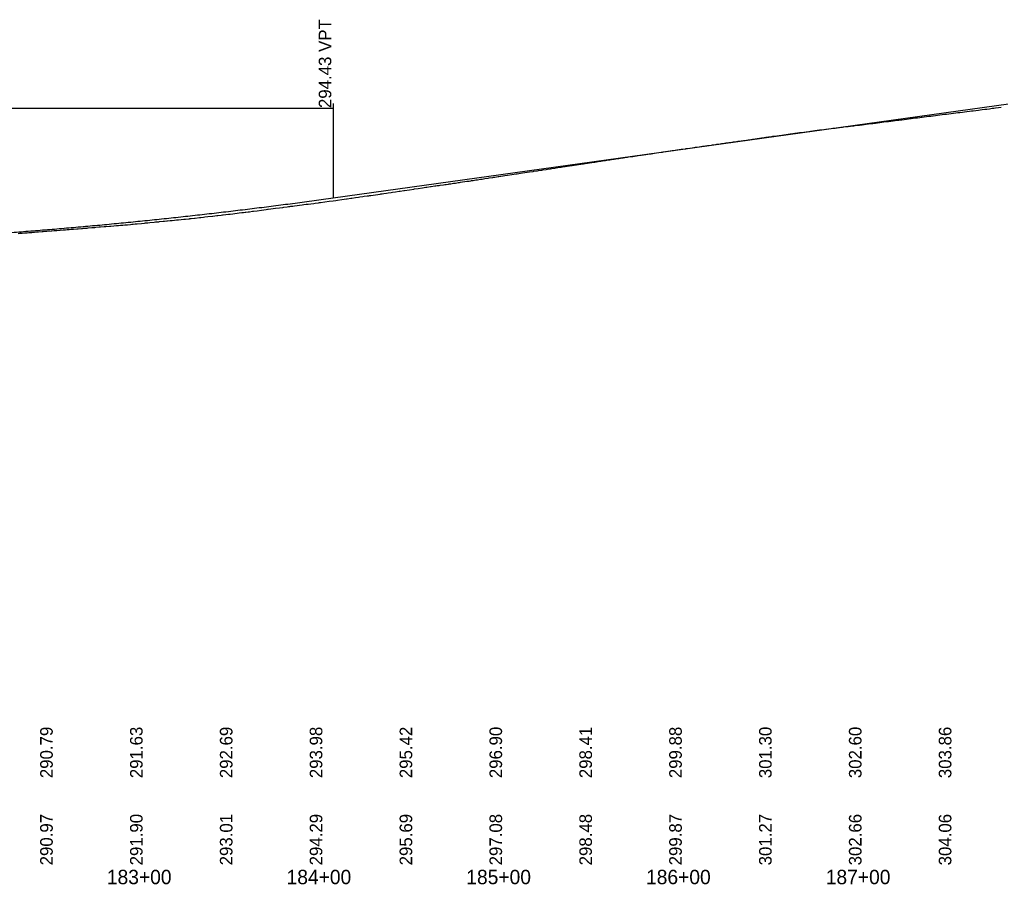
# Model space of a CAD drawing. Extents: x 1838386 to 1955906, y 719739 to 834437.
# Drawn here: x 1895594 to 1896139, y 826223 to 826704 of the extents above; entities that cross this region are included whole.
import ezdxf

# ---------------------------------------------------------------- set-up
doc = ezdxf.new("R2010")
doc.units = 0
for name, color, linetype in [('RD_DDB_Profile_EX', 7, 'Continuous'), ('RD_DDB_Profile_PR', 7, 'Continuous'), ('RD_DDB_StaTX', 7, 'Continuous'), ('RD_DDB_StripGrade', 7, 'Continuous'), ('RD_DDB_VCLbl', 7, 'Continuous')]:
    doc.layers.add(name, color=color, linetype=linetype)

msp = doc.modelspace()

# ---------------------------------------------------------------- linework, layer by layer
at = {"layer": 'RD_DDB_Profile_EX'}
for points in [[(1896023.79, 826641.09), (1896024.99, 826641.26), (1896026.44, 826641.45), (1896027.51, 826641.59), (1896028.76, 826641.75), (1896030, 826641.92), (1896031.24, 826642.09), (1896032.71, 826642.28), (1896033.71, 826642.41), (1896034.92, 826642.57), (1896036.19, 826642.74), (1896037.38, 826642.89), (1896038.67, 826643.06), (1896038.97, 826643.1), (1896039.85, 826643.21), (1896041.14, 826643.37), (1896042.32, 826643.51), (1896043.63, 826643.68), (1896045.24, 826643.89), (1896046.12, 826644), (1896047.47, 826644.17), (1896048.6, 826644.31), (1896049.74, 826644.45), (1896051.08, 826644.62), (1896051.5, 826644.67), (1896052.21, 826644.76), (1896053.56, 826644.92), (1896054.69, 826645.06), (1896056.04, 826645.23), (1896057.38, 826645.4), (1896057.77, 826645.44), (1896058.52, 826645.54), (1896059.88, 826645.7), (1896061.01, 826645.84), (1896062.39, 826646.01), (1896063.49, 826646.15), (1896064.04, 826646.22), (1896064.6, 826646.29), (1896065.97, 826646.46), (1896067.08, 826646.6), (1896068.44, 826646.77), (1896069.78, 826646.94), (1896070.3, 826647), (1896070.93, 826647.08), (1896072.32, 826647.26), (1896073.42, 826647.4), (1896074.54, 826647.54), (1896075.9, 826647.71), (1896076.57, 826647.79), (1896077.03, 826647.85), (1896078.37, 826648.01), (1896079.69, 826648.18), (1896080.86, 826648.33), (1896082.22, 826648.51), (1896082.83, 826648.59), (1896083.34, 826648.65), (1896084.49, 826648.8), (1896085.81, 826648.97), (1896087.1, 826649.13), (1896088.3, 826649.29), (1896089.1, 826649.39), (1896089.62, 826649.45), (1896090.79, 826649.6), (1896091.97, 826649.75), (1896093.26, 826649.9), (1896094.51, 826650.06), (1896095.36, 826650.17), (1896095.74, 826650.22), (1896097.02, 826650.38), (1896098.24, 826650.54), (1896099.46, 826650.7), (1896100.7, 826650.85), (1896101.63, 826650.97), (1896101.97, 826651.01), (1896103.2, 826651.17), (1896104.43, 826651.32), (1896105.71, 826651.49), (1896107, 826651.66), (1896108.19, 826651.81), (1896109.35, 826651.96), (1896110.7, 826652.12), (1896111.9, 826652.26), (1896113.21, 826652.44), (1896114.57, 826652.61), (1896115.69, 826652.75), (1896116.79, 826652.89), (1896118.21, 826653.07), (1896119.33, 826653.2), (1896120.7, 826653.37), (1896122.12, 826653.55), (1896123.2, 826653.67), (1896124.28, 826653.81), (1896125.71, 826653.99), (1896127.16, 826654.17), (1896128.18, 826654.29), (1896129.19, 826654.42), (1896130.7, 826654.61), (1896131.74, 826654.74), (1896133.2, 826654.93), (1896134.71, 826655.13), (1896135.7, 826655.25)], [(1896135.7, 826655.25), (1896136.7, 826655.38), (1896138.21, 826655.57), (1896139.76, 826655.77)], [(1895900.8, 826623.32), (1895901.14, 826623.37), (1895902.16, 826623.53), (1895903.44, 826623.72), (1895904.65, 826623.89), (1895905.85, 826624.07), (1895907.41, 826624.31), (1895908.27, 826624.44), (1895909.62, 826624.64), (1895910.67, 826624.8), (1895912.11, 826625.02), (1895913.08, 826625.17), (1895913.67, 826625.25), (1895914.59, 826625.39), (1895915.5, 826625.52), (1895917.07, 826625.76), (1895917.91, 826625.88), (1895919.56, 826626.13), (1895919.94, 826626.19), (1895920.32, 826626.25), (1895922.05, 826626.51), (1895923.85, 826626.77), (1895924.51, 826626.87), (1895926.4, 826627.16), (1895926.99, 826627.24), (1895928.96, 826627.54), (1895929.47, 826627.61), (1895931.51, 826627.91), (1895931.95, 826627.97), (1895932.47, 826628.05), (1895934.06, 826628.29), (1895934.44, 826628.34), (1895934.8, 826628.39), (1895936.91, 826628.71), (1895938.73, 826628.97), (1895939.4, 826629.07), (1895942.05, 826629.47), (1895944.48, 826629.82), (1895945, 826629.89), (1895946.9, 826630.17), (1895949.33, 826630.52), (1895951.26, 826630.8), (1895951.81, 826630.89), (1895954.3, 826631.24), (1895956.79, 826631.6), (1895957.53, 826631.71), (1895959.26, 826631.96), (1895961.75, 826632.31), (1895963.91, 826632.63), (1895964.24, 826632.67), (1895964.57, 826632.72), (1895966.72, 826633.01), (1895968.78, 826633.31), (1895969.2, 826633.37), (1895969.63, 826633.43), (1895970.06, 826633.49), (1895971.67, 826633.72), (1895973.65, 826634), (1895974.16, 826634.07), (1895976.32, 826634.38), (1895976.64, 826634.42), (1895978.53, 826634.69), (1895979.13, 826634.78), (1895980.96, 826635.04), (1895981.6, 826635.13), (1895982.59, 826635.27), (1895983.4, 826635.39), (1895984.09, 826635.48), (1895985.84, 826635.73), (1895986.57, 826635.84), (1895988.29, 826636.08), (1895989.05, 826636.18), (1895990.73, 826636.42), (1895991.53, 826636.54), (1895993.18, 826636.76), (1895994.01, 826636.88), (1895995.12, 826637.04), (1895995.62, 826637.11), (1895996.49, 826637.23), (1895998.06, 826637.44), (1895998.97, 826637.57), (1896000.51, 826637.79), (1896001.46, 826637.93), (1896002.96, 826638.14), (1896003.93, 826638.28), (1896005.41, 826638.49), (1896006.41, 826638.63), (1896007.86, 826638.84), (1896008.89, 826638.99), (1896010.31, 826639.2), (1896011.37, 826639.35), (1896012.77, 826639.55), (1896013.91, 826639.72), (1896014.96, 826639.87), (1896016.34, 826640.06), (1896017.68, 826640.25), (1896018.82, 826640.41), (1896020.18, 826640.6), (1896021.29, 826640.75), (1896022.47, 826640.91), (1896023.79, 826641.09)], [(1895780.45, 826605.44), (1895782.23, 826605.69), (1895782.93, 826605.8), (1895784.6, 826606.04), (1895785.43, 826606.15), (1895786.97, 826606.37), (1895787.92, 826606.51), (1895788.37, 826606.58), (1895788.99, 826606.67), (1895790.4, 826606.86), (1895791.62, 826607.04), (1895792.89, 826607.22), (1895794.26, 826607.42), (1895794.63, 826607.47), (1895795.36, 826607.57), (1895796.36, 826607.72), (1895797.86, 826607.94), (1895798.74, 826608.06), (1895800.35, 826608.3), (1895801.11, 826608.41), (1895802.83, 826608.67), (1895804.75, 826608.96), (1895805.3, 826609.04), (1895807.37, 826609.34), (1895807.78, 826609.4), (1895810.52, 826609.81), (1895812.9, 826610.16), (1895813.43, 826610.24), (1895815.49, 826610.56), (1895817.88, 826610.9), (1895819.69, 826611.16), (1895820.21, 826611.24), (1895822.33, 826611.56), (1895822.69, 826611.61), (1895824.71, 826611.91), (1895825.18, 826611.98), (1895825.96, 826612.09), (1895827.09, 826612.24), (1895827.67, 826612.32), (1895829.46, 826612.59), (1895830.16, 826612.69), (1895830.92, 826612.8), (1895832.22, 826612.99), (1895832.64, 826613.05), (1895833.53, 826613.18), (1895835.13, 826613.42), (1895836.13, 826613.56), (1895837.6, 826613.77), (1895838.49, 826613.9), (1895838.93, 826613.97), (1895840.08, 826614.14), (1895841.32, 826614.32), (1895842.57, 826614.51), (1895843.7, 826614.67), (1895844.75, 826614.83), (1895845.06, 826614.87), (1895846.09, 826615.02), (1895847.55, 826615.24), (1895848.47, 826615.37), (1895850.03, 826615.62), (1895851.02, 826615.77), (1895851.73, 826615.88), (1895852.5, 826615.99), (1895854.33, 826616.26), (1895854.98, 826616.36), (1895856.93, 826616.66), (1895857.47, 826616.74), (1895857.97, 826616.81), (1895859.95, 826617.12), (1895860.36, 826617.18), (1895862.45, 826617.49), (1895862.75, 826617.54), (1895863.55, 826617.66), (1895865.15, 826617.91), (1895867.54, 826618.27), (1895869.94, 826618.64), (1895870.51, 826618.73), (1895872.38, 826619.02), (1895874.84, 826619.39), (1895876.08, 826619.57), (1895877.33, 826619.76), (1895879.46, 826620.06), (1895879.82, 826620.12), (1895881.86, 826620.42), (1895882.35, 826620.49), (1895884.26, 826620.78), (1895884.79, 826620.87), (1895886.66, 826621.15), (1895887.28, 826621.24), (1895888.61, 826621.45), (1895889.06, 826621.51), (1895889.76, 826621.62), (1895891.47, 826621.88), (1895892.24, 826622), (1895893.08, 826622.13), (1895894.88, 826622.4), (1895895.66, 826622.52), (1895897.21, 826622.76), (1895898.23, 826622.92), (1895899.69, 826623.14), (1895900.8, 826623.32)], [(1895653.59, 826590.37), (1895655.28, 826590.52), (1895656.07, 826590.59), (1895656.8, 826590.66), (1895658, 826590.77), (1895658.57, 826590.82), (1895659.05, 826590.86), (1895661.37, 826591.09), (1895663.06, 826591.27), (1895663.68, 826591.33), (1895664.96, 826591.45), (1895666.02, 826591.55), (1895668.52, 826591.81), (1895669.33, 826591.88), (1895670.57, 826592), (1895671.02, 826592.04), (1895671.55, 826592.1), (1895673.51, 826592.28), (1895674.26, 826592.35), (1895675.59, 826592.48), (1895676.01, 826592.52), (1895677.46, 826592.66), (1895678.48, 826592.76), (1895679.78, 826592.88), (1895680.98, 826593), (1895682.11, 826593.11), (1895683.47, 826593.24), (1895685.06, 826593.41), (1895685.94, 826593.49), (1895687.75, 826593.68), (1895688.12, 826593.72), (1895688.44, 826593.75), (1895689.01, 826593.81), (1895690.94, 826594.03), (1895691.35, 826594.07), (1895693.67, 826594.33), (1895694.39, 826594.41), (1895695.9, 826594.58), (1895696.72, 826594.68), (1895698.38, 826594.86), (1895700.89, 826595.14), (1895701.22, 826595.17), (1895703.38, 826595.42), (1895703.91, 826595.49), (1895705.87, 826595.71), (1895706.59, 826595.8), (1895706.92, 826595.84), (1895708.34, 826596), (1895709.86, 826596.18), (1895710.83, 826596.3), (1895712.2, 826596.46), (1895713.33, 826596.6), (1895714.63, 826596.77), (1895715.8, 826596.91), (1895717.31, 826597.09), (1895718.3, 826597.22), (1895719.13, 826597.32), (1895719.45, 826597.36), (1895720.78, 826597.53), (1895721.48, 826597.61), (1895723.28, 826597.84), (1895723.82, 826597.91), (1895725.76, 826598.17), (1895728.23, 826598.49), (1895730.78, 826598.82), (1895731.49, 826598.92), (1895731.98, 826598.98), (1895733.35, 826599.16), (1895736.02, 826599.5), (1895738.25, 826599.79), (1895740.09, 826600.02), (1895740.67, 826600.1), (1895742.45, 826600.32), (1895743.17, 826600.41), (1895743.99, 826600.52), (1895744.51, 826600.59), (1895745.66, 826600.74), (1895746.66, 826600.86), (1895748.14, 826601.05), (1895749.42, 826601.21), (1895750.78, 826601.4), (1895751.78, 826601.52), (1895753.12, 826601.7), (1895754.13, 826601.83), (1895755.6, 826602.02), (1895757.27, 826602.25), (1895758.08, 826602.35), (1895759.93, 826602.6), (1895760.57, 826602.68), (1895761.13, 826602.76), (1895763.49, 826603.08), (1895765.85, 826603.4), (1895768.03, 826603.71), (1895769.57, 826603.92), (1895770.5, 826604.05), (1895773, 826604.39), (1895775.49, 826604.75), (1895775.84, 826604.8), (1895777.98, 826605.1), (1895778.45, 826605.17), (1895780.45, 826605.44)], [(1895592.77, 826585.52), (1895593.8, 826585.6), (1895594.15, 826585.62), (1895595.07, 826585.69), (1895596.29, 826585.77), (1895597.83, 826585.9), (1895598.79, 826585.96), (1895599.57, 826586.02), (1895600.41, 826586.09), (1895601.28, 826586.16), (1895601.86, 826586.2), (1895603.78, 826586.36), (1895604.15, 826586.38), (1895606.25, 826586.55), (1895606.68, 826586.58), (1895607.92, 826586.68), (1895608.72, 826586.75), (1895611.25, 826586.94), (1895611.58, 826586.97), (1895612.94, 826587.07), (1895613.74, 826587.13), (1895614.33, 826587.18), (1895616.24, 826587.33), (1895617.79, 826587.44), (1895618.71, 826587.51), (1895619.21, 826587.55), (1895620.09, 826587.61), (1895621.21, 826587.7), (1895622.39, 826587.79), (1895623.7, 826587.9), (1895625.47, 826588.05), (1895626.19, 826588.1), (1895628.02, 826588.26), (1895628.69, 826588.31), (1895629.23, 826588.35), (1895631.18, 826588.52), (1895631.74, 826588.57), (1895633.84, 826588.75), (1895635.52, 826588.89), (1895636.14, 826588.94), (1895638, 826589.1), (1895638.64, 826589.16), (1895640.7, 826589.32), (1895641.14, 826589.36), (1895641.67, 826589.4), (1895643.64, 826589.56), (1895644.41, 826589.62), (1895646.12, 826589.75), (1895647.54, 826589.86), (1895648.6, 826589.95), (1895649.86, 826590.06), (1895650.53, 826590.12), (1895651.11, 826590.17), (1895652.18, 826590.25), (1895653.59, 826590.37)]]:
    msp.add_lwpolyline(points, dxfattribs=at)
at = {"layer": 'RD_DDB_Profile_PR'}
msp.add_line((1895768.08, 826605.28), (1896443.08, 826699.43), dxfattribs=at)
msp.add_spline([(1895238.08, 826581.84), (1895248.68, 826581.32), (1895259.28, 826580.84), (1895269.88, 826580.4), (1895280.48, 826580), (1895291.08, 826579.64), (1895301.68, 826579.32), (1895312.28, 826579.04), (1895322.88, 826578.8), (1895333.48, 826578.61), (1895344.08, 826578.45), (1895354.68, 826578.33), (1895365.28, 826578.25), (1895375.88, 826578.22), (1895386.48, 826578.22), (1895397.08, 826578.27), (1895407.68, 826578.35), (1895418.28, 826578.48), (1895428.88, 826578.64), (1895439.48, 826578.85), (1895450.08, 826579.1), (1895460.68, 826579.38), (1895471.28, 826579.71), (1895481.88, 826580.08), (1895492.48, 826580.49), (1895503.08, 826580.93), (1895513.68, 826581.42), (1895524.28, 826581.95), (1895534.88, 826582.52), (1895545.48, 826583.13), (1895556.08, 826583.78), (1895566.68, 826584.47), (1895577.28, 826585.2), (1895587.88, 826585.98), (1895598.48, 826586.79), (1895609.08, 826587.64), (1895619.68, 826588.53), (1895630.28, 826589.47), (1895640.88, 826590.44), (1895651.48, 826591.45), (1895662.08, 826592.51), (1895672.68, 826593.6), (1895683.28, 826594.74), (1895693.88, 826595.91), (1895704.48, 826597.13), (1895715.08, 826598.39), (1895725.68, 826599.68), (1895736.28, 826601.02), (1895746.88, 826602.4), (1895757.48, 826603.82), (1895768.08, 826605.28)], degree=3, dxfattribs=at)
at = {"layer": 'RD_DDB_VCLbl'}
for p, q in [((1895238.08, 826655.28), (1895768.08, 826655.28)), ((1895768.08, 826657.78), (1895768.08, 826605.28))]:
    msp.add_line(p, q, dxfattribs=at)

# ---------------------------------------------------------------- texts
at = {"layer": 'RD_DDB_StaTX'}
for s, p in [('183+00', (1895642.18, 826223.35)), ('184+00', (1895742.18, 826223.35)), ('185+00', (1895842.18, 826223.35)), ('186+00', (1895942.18, 826223.35)), ('187+00', (1896042.18, 826223.35))]:
    msp.add_text(s, height=8, dxfattribs=at).set_placement(p)
at = {"layer": 'RD_DDB_StripGrade'}
for s, p in [('294.43 VPT', (1895767.08, 826655.28)), ('290.79', (1895612.08, 826282.35)), ('291.63', (1895662.08, 826282.35)), ('292.69', (1895712.08, 826282.35)), ('293.98', (1895762.08, 826282.35)), ('295.42', (1895812.08, 826282.35)), ('296.90', (1895862.08, 826282.35)), ('298.41', (1895912.08, 826282.35)), ('299.88', (1895962.08, 826282.35)), ('301.30', (1896012.08, 826282.35)), ('302.60', (1896062.08, 826282.35)), ('303.86', (1896112.08, 826282.35)), ('290.97', (1895612.08, 826233.83)), ('291.90', (1895662.08, 826233.83)), ('293.01', (1895712.08, 826233.83)), ('294.29', (1895762.08, 826233.83)), ('295.69', (1895812.08, 826233.83)), ('297.08', (1895862.08, 826233.83)), ('298.48', (1895912.08, 826233.83)), ('299.87', (1895962.08, 826233.83)), ('301.27', (1896012.08, 826233.83)), ('302.66', (1896062.08, 826233.83)), ('304.06', (1896112.08, 826233.83))]:
    msp.add_text(s, height=7, rotation=90, dxfattribs=at).set_placement(p)

doc.saveas('drawing.dxf')
